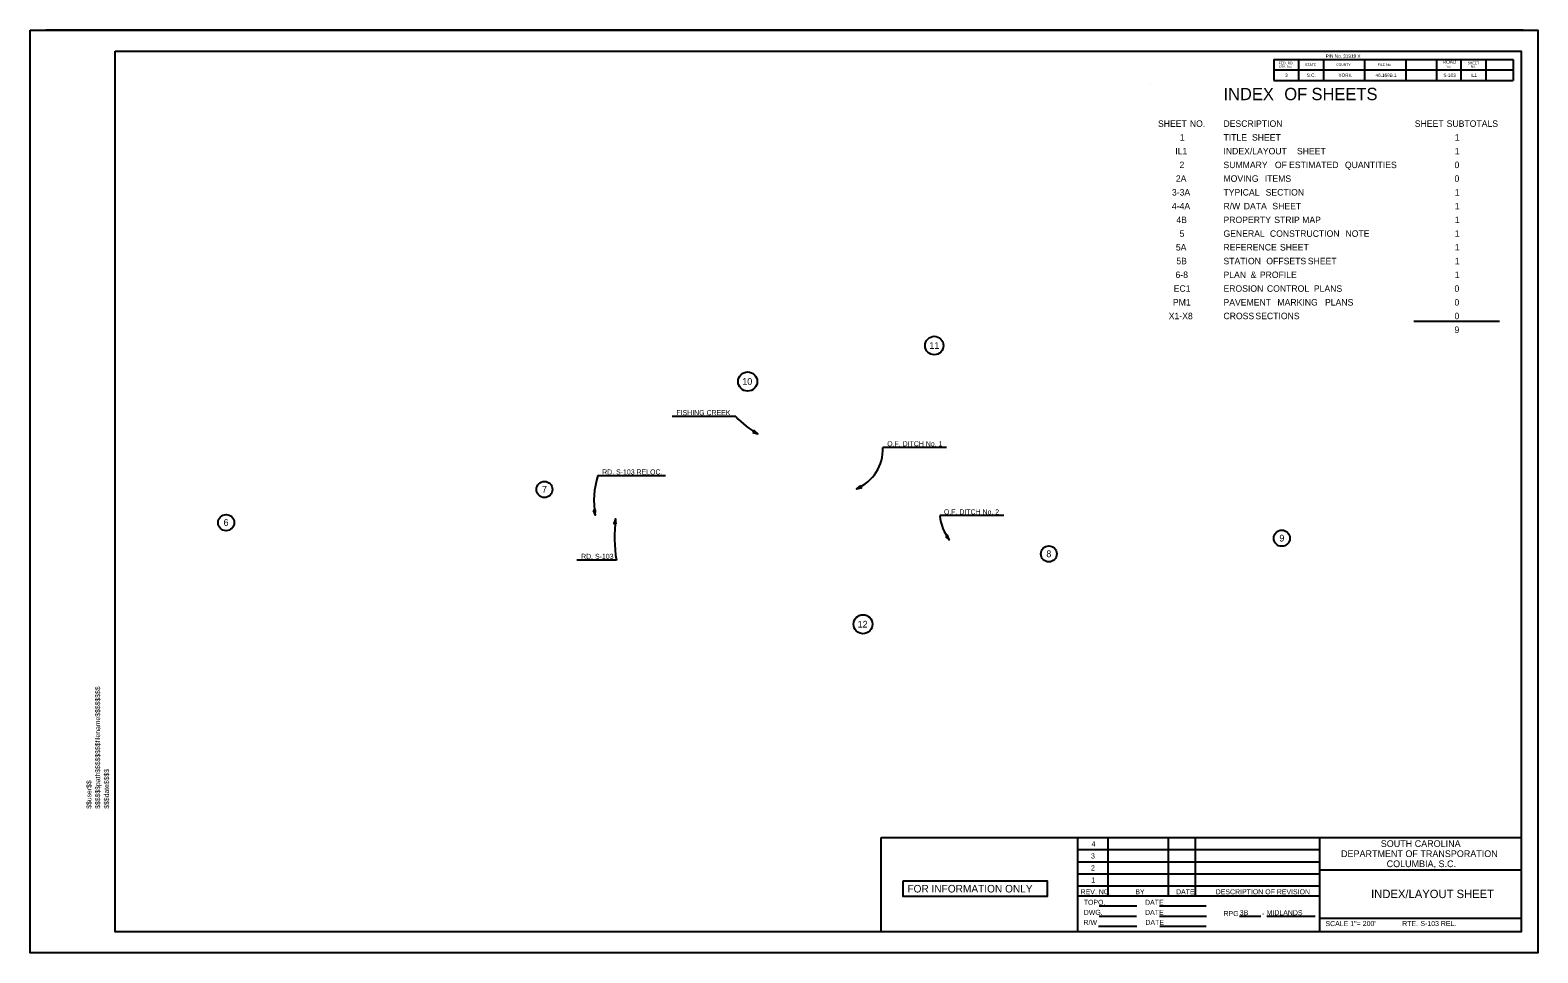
# Model space of a CAD drawing. Extents: x 8134 to 11793, y 3225 to 13425.
# Drawn here: x 9981 to 11777, y 8875 to 9975 of the extents above; entities that cross this region are included whole.
import ezdxf

# ---------------------------------------------------------------- set-up
doc = ezdxf.new("R2010")
doc.units = 0
for name, color, linetype in [('RD_EX_DV_TX_Prop', 7, 'Continuous'), ('RD_SHT_Bndy', 7, 'Continuous'), ('RD_SHT_ID', 7, 'Continuous'), ('RD_SHT_IplotShp', 7, 'Continuous'), ('RD_SHT_TX', 7, 'Continuous'), ('RD_TX_RoadID', 7, 'Continuous'), ('RD_TX_StaOff', 7, 'Continuous'), ('RD_TX_TitleSht', 7, 'Continuous')]:
    doc.layers.add(name, color=color, linetype=linetype)

msp = doc.modelspace()

# ---------------------------------------------------------------- linework, layer by layer
at = {"layer": 'RD_EX_DV_TX_Prop'}
for centre, radius in [((11058.4, 9599), 11), ((10836.1, 9556.1), 11.4), ((10594, 9427.4), 9.58), ((10214.8, 9387.9), 9.63), ((11472.4, 9369.3), 9.64), ((11194.9, 9350.6), 9.5), ((10973.5, 9266.8), 11.3)]:
    msp.add_circle(centre, radius, dxfattribs=at)
at = {"layer": 'RD_SHT_Bndy'}
for p, q in [((10000, 9975), (11760, 9975)), ((11760, 9975), (10000, 9975)), ((11463.1, 9940), (11463.1, 9915)), ((11463.1, 9940), (11748.1, 9940)), ((11492.1, 9940), (11492.1, 9915)), ((11522.1, 9940), (11522.1, 9915)), ((11571.1, 9940), (11571.1, 9915)), ((11620.1, 9940), (11620.1, 9915)), ((11656.6, 9940), (11656.6, 9915)), ((11685.6, 9940), (11685.6, 9915)), ((11715.6, 9940), (11715.6, 9915)), ((11748.1, 9940), (11748.1, 9915)), ((11463.1, 9927.5), (11748.1, 9927.5)), ((11463.1, 9915), (11748.1, 9915)), ((10995, 9012.5), (11757.6, 9012.5)), ((10995, 8900), (10995, 9012.5)), ((11229.6, 8900), (11229.6, 9012.5)), ((11229.6, 9012.5), (11229.6, 9012.5)), ((11229.6, 8998.1), (11517.6, 8998.1)), ((11265.6, 8942.8), (11265.6, 9012.5)), ((11337.6, 8942.8), (11337.6, 9012.5)), ((11369.4, 8942.9), (11369.4, 9012.5)), ((11517.6, 8900), (11517.6, 9012.5)), ((11229.6, 8983.7), (11517.6, 8983.7)), ((11229.6, 8969.3), (11517.6, 8969.3)), ((11517.6, 8974.1), (11757.6, 8974.1)), ((11229.6, 8954.9), (11517.6, 8954.9)), ((11229.6, 8942.9), (11517.6, 8942.9)), ((11255, 8930.9), (11299.9, 8930.9)), ((11326.8, 8930.9), (11382.1, 8930.9)), ((11255, 8918.9), (11299.5, 8918.9)), ((11326.8, 8918.9), (11382.5, 8918.9)), ((11422.1, 8918.9), (11447.3, 8918.9)), ((11454.5, 8918.9), (11512, 8918.9)), ((11517.6, 8916.5), (11757.6, 8916.5)), ((11254.2, 8906.9), (11299.9, 8906.9)), ((11327.2, 8906.9), (11382.1, 8906.9)), ((11760, 8875), (10000, 8875)), ((11760, 8875), (10000, 8875))]:
    msp.add_line(p, q, dxfattribs=at)
msp.add_lwpolyline([(10082.6, 9950), (11757.6, 9950), (11757.6, 8900), (10082.6, 8900)], close=True, dxfattribs=at)
at = {"layer": 'RD_SHT_IplotShp'}
msp.add_lwpolyline([(9981.4, 9975), (11777.4, 9975), (11777.4, 8875), (9981.4, 8875)], close=True, dxfattribs=at)
at = {"layer": 'RD_SHT_TX'}
msp.add_lwpolyline([(11021.4, 8961), (11192.9, 8961), (11192.9, 8942), (11021.4, 8942)], close=True, dxfattribs=at)
at = {"layer": 'RD_TX_RoadID'}
for p, q in [((10822.1, 9514.5), (10746.2, 9514.5)), ((11072.9, 9477.4), (10997.3, 9477.4)), ((10738.2, 9443.8), (10657.8, 9443.8)), ((11141.1, 9396.2), (11064.9, 9396.2)), ((10679.7, 9343.2), (10632.7, 9343.2))]:
    msp.add_line(p, q, dxfattribs=at)
for points in [[(10842.4, 9495.2), (10848.2, 9493.8), (10843.9, 9497.9)], [(10970.7, 9432), (10965.9, 9428.3), (10971.9, 9429.2)], [(10651.9, 9402.2), (10654.4, 9396.8), (10655, 9402.7)], [(10679.6, 9386.3), (10678.8, 9392.3), (10676.5, 9386.7)], [(11071.6, 9371.2), (11076.2, 9367.4), (11074.1, 9373)]]:
    msp.add_lwpolyline(points, close=True, dxfattribs=at)
for centre, radius, start, end in [((10894.2, 9578.6), 96.5, 221.6835, 241.5684), ((10945.7, 9475.8), 51.6, 293.0973, 1.7888), ((10753.5, 9413.4), 100.5, 162.3361, 189.5096), ((11128.8, 9404.7), 64.5, 187.6219, 215.3784), ((10856.8, 9371.2), 179.3, 173.2398, 188.986)]:
    msp.add_arc(centre, radius, start, end, dxfattribs=at)
at = {"layer": 'RD_TX_StaOff'}
msp.add_line((11315.5, 9910.6), (11315.5, 9910.6), dxfattribs=at)
at = {"layer": 'RD_TX_TitleSht'}
msp.add_line((11629.5, 9628), (11731.8, 9628), dxfattribs=at)

# ---------------------------------------------------------------- texts
at = {"layer": 'RD_EX_DV_TX_Prop'}
for s, p in [('11', (11052.5, 9595)), ('10', (10829.7, 9552.2)), ('7', (10591.1, 9423.6)), ('6', (10211.8, 9384)), ('9', (11469.5, 9365.4)), ('8', (11191.9, 9346.7)), ('12', (10967.1, 9262.8))]:
    msp.add_text(s, height=8, dxfattribs=at).set_placement(p)
at = {"layer": 'RD_SHT_ID'}
for s, p in [('$$$$$$path$$$$$$$$filename$$$$$$$$', (10064.8, 9046.8)), ('$$$date$$$$', (10075.3, 9046.8)), ('$$user$$', (10054.3, 9046.8))]:
    msp.add_text(s, height=5.88, rotation=90, dxfattribs=at).set_placement(p)
at = {"layer": 'RD_SHT_TX'}
for s, height, p in [('FED. RD.', 3, (11468.7, 9934.3)), ('DIV. No.', 3, (11469.3, 9930.2)), ('STATE', 3, (11500.1, 9932.3)), ('PIN No. 31919 X   ', 4, (11524.7, 9942)), ('COUNTY', 3, (11537.1, 9932.3)), ('FILE No.', 3, (11586.6, 9932.3)), ('      ROAD      ', 4, (11655, 9935.1)), ('No.', 3, (11667.9, 9930.2)), ('SHEET', 3, (11693.7, 9934.3)), ('No.', 3, (11697.4, 9930.2)), ('3', 4, (11476.4, 9919.3)), ('S.C.', 4, (11502.1, 9919.3)), ('      YORK      ', 4, (11530.7, 9919.3)), ('   46.169B.1    ', 4, (11579.4, 9919.3)), ('     S-103      ', 4, (11657.2, 9919.3)), ('      IL1       ', 4, (11688, 9919.3)), ('4', 6.24, (11245.8, 9001.9)), ('SOUTH CAROLINA', 8, (11590.3, 9001.2)), ('3', 6.24, (11245, 8987.5)), ('DEPARTMENT OF TRANSPORATION', 8, (11543, 8989.2)), ('COLUMBIA, S.C.', 8, (11597.3, 8977.2)), ('2', 6.24, (11245, 8973.1)), ('1', 6.24, (11245.4, 8958.7)), ('FOR INFORMATION ONLY', 9, (11026.4, 8947)), ('REV. NO.', 6, (11232.7, 8944.8)), ('BY', 6, (11297.9, 8944.8)), ('DATE', 6, (11346.4, 8944.8)), ('DESCRIPTION OF REVISION', 6, (11393.7, 8944.8)), ('      INDEX/LAYOUT SHEET       ', 10, (11556.5, 8940.3)), ('TOPO.', 6, (11236.5, 8932.3)), ('DWG.', 6, (11236.5, 8920.3)), ('DATE', 6, (11309.5, 8932.3)), ('DATE', 6, (11309.5, 8920.3)), ('R/W', 6, (11236.2, 8908.3)), ('DATE', 6, (11309.9, 8908.3)), ('RPG', 6, (11403, 8918.9)), ('3B    ', 6, (11422.3, 8919.9)), ('-', 6, (11448.7, 8918.9)), ('MIDLANDS   ', 6, (11454.3, 8919.9)), ('SCALE 1"=', 6, (11524.4, 8906.9)), ("200'       ", 6, (11568.8, 8907)), ('RTE.', 6, (11615.8, 8906.9)), ('S-103 REL. ', 6, (11637.5, 8907))]:
    msp.add_text(s, height=height, dxfattribs=at).set_placement(p)
at = {"layer": 'RD_TX_RoadID'}
for s, p in [('FISHING CREEK', (10751.2, 9516)), ('O.F. DITCH No. 1', (11002.3, 9478.9)), ('RD. S-103 RELOC.', (10662.8, 9445.3)), ('O.F. DITCH No. 2', (11069.9, 9397.7)), ('RD. S-103', (10637.7, 9344.7))]:
    msp.add_text(s, height=6, dxfattribs=at).set_placement(p)
at = {"layer": 'RD_TX_TitleSht'}
for s, height, p in [('INDEX', 14.7, (11402.9, 9891.5)), (' OF', 14.7, (11469.9, 9891.5)), (' SHEETS', 14.7, (11502.3, 9891.5)), ('SHEET', 7.7, (11324.9, 9859.7)), (' NO.', 7.7, (11360, 9859.7)), ('DESCRIPTION', 7.7, (11402.9, 9859.7)), ('SHEET', 7.7, (11630.8, 9859.7)), (' SUBTOTALS', 7.7, (11665.9, 9859.7)), ('1', 7.7, (11350.9, 9843.3)), ('TITLE', 7.7, (11402.9, 9843.3)), (' SHEET', 7.7, (11434, 9843.3)), ('1', 7.7, (11678.5, 9843.3)), ('IL1', 7.7, (11345.5, 9826.9)), ('INDEX/LAYOUT', 7.7, (11402.9, 9826.9)), (' SHEET', 7.7, (11487.6, 9826.9)), ('1', 7.7, (11678.5, 9826.9)), ('2', 7.7, (11350.5, 9810.5)), ('SUMMARY', 7.7, (11402.9, 9810.5)), (' OF', 7.7, (11461.3, 9810.5)), (' ESTIMATED', 7.7, (11478.2, 9810.5)), (' QUANTITIES', 7.7, (11544.7, 9810.5)), ('0', 7.7, (11678.1, 9810.5)), ('2A', 7.7, (11346.2, 9794.2)), ('MOVING', 7.7, (11402.9, 9794.2)), (' ITEMS', 7.7, (11449.2, 9794.2)), ('0', 7.7, (11678.1, 9794.2)), ('3-3A', 7.7, (11341.5, 9777.8)), ('TYPICAL', 7.7, (11402.9, 9777.8)), (' SECTION', 7.7, (11450.3, 9777.8)), ('1', 7.7, (11678.5, 9777.8)), ('4-4A', 7.7, (11341.5, 9761.4)), ('4B', 7.7, (11346.8, 9745)), ('R/W', 7.7, (11402.9, 9761.4)), ('PROPERTY', 7.7, (11402.9, 9745)), (' DATA', 7.7, (11424.2, 9761.4)), (' SHEET', 7.7, (11458.3, 9761.4)), (' STRIP', 7.7, (11460.6, 9745)), (' MAP', 7.7, (11493.8, 9745)), ('1', 7.7, (11678.5, 9761.4)), ('1', 7.7, (11678.5, 9745)), ('5', 7.7, (11350.6, 9728.6)), ('GENERAL', 7.7, (11402.9, 9728.6)), (' CONSTRUCTION', 7.7, (11455.4, 9728.6)), (' NOTE', 7.7, (11545.4, 9728.6)), ('1', 7.7, (11678.5, 9728.6)), ('5A', 7.7, (11346.2, 9712.3)), ('REFERENCE', 7.7, (11402.9, 9712.3)), (' SHEET', 7.7, (11467.3, 9712.3)), ('1', 7.7, (11678.5, 9712.3)), ('5B', 7.7, (11346.8, 9695.9)), ('STATION', 7.7, (11402.9, 9695.9)), (' OFFSETS', 7.7, (11451.1, 9695.9)), (' SHEET', 7.7, (11500.5, 9695.9)), ('1', 7.7, (11678.5, 9695.9)), ('6-8', 7.7, (11345.8, 9679.5)), ('PLAN', 7.7, (11402.9, 9679.5)), (' &', 7.7, (11432.3, 9679.5)), (' PROFILE', 7.7, (11443.4, 9679.5)), ('1', 7.7, (11678.5, 9679.5)), ('EC1', 7.7, (11343.6, 9663.1)), ('EROSION', 7.7, (11402.9, 9663.1)), (' CONTROL', 7.7, (11451.8, 9663.1)), (' PLANS', 7.7, (11507.7, 9663.1)), ('0', 7.7, (11678.1, 9663.1)), ('PM1', 7.7, (11342.7, 9646.7)), ('PAVEMENT', 7.7, (11402.9, 9646.7)), (' MARKING', 7.7, (11464.3, 9646.7)), (' PLANS', 7.7, (11521, 9646.7)), ('0', 7.7, (11678.1, 9646.7)), ('X1-X8', 7.7, (11337.7, 9630.4)), ('CROSS', 7.7, (11402.9, 9630.4)), (' SECTIONS', 7.7, (11438.1, 9630.4)), ('0', 7.7, (11678.1, 9630.4)), ('9', 7.7, (11678.1, 9614))]:
    msp.add_text(s, height=height, dxfattribs=at).set_placement(p)

doc.saveas('drawing.dxf')
